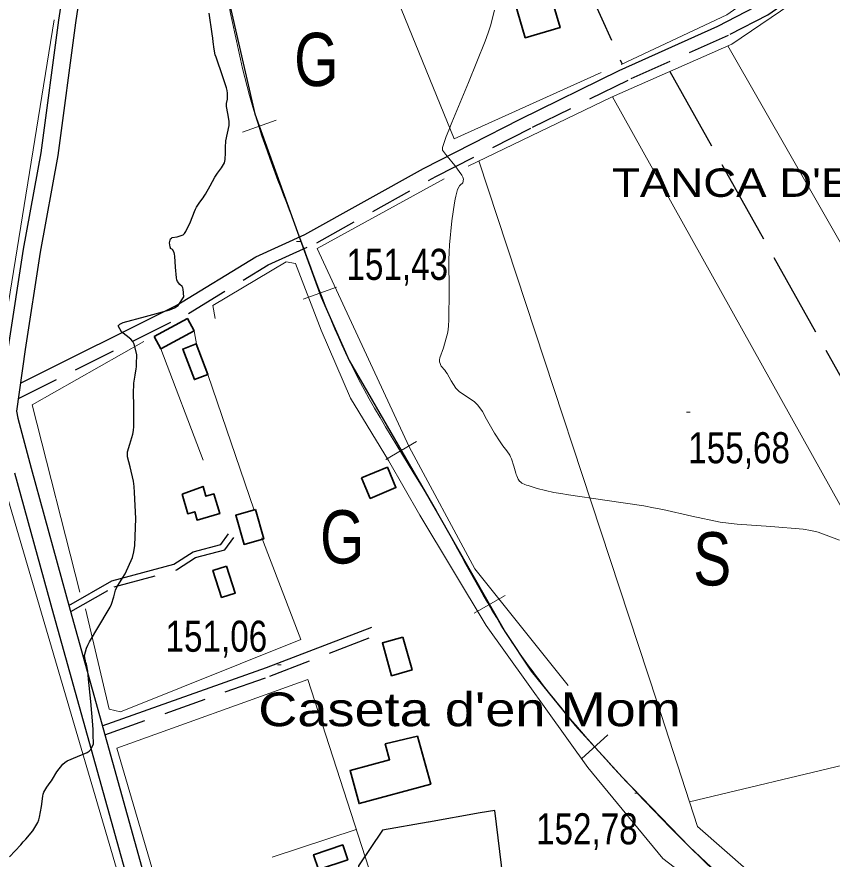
# Model space of a CAD drawing. Extents: x -807245 to 6129983, y -54972206 to 262146364.
# Drawn here: x 489087.2 to 489316.8, y 4382070.1 to 4382307.3 of the extents above; entities that cross this region are included whole.
import ezdxf
from ezdxf.enums import TextEntityAlignment as Align

# ---------------------------------------------------------------- set-up
doc = ezdxf.new("R2010")
doc.units = 0
doc.header["$LTSCALE"] = 4
doc.linetypes.add('LONG_DASHED', pattern=[7.5, 6, -1.5])
doc.linetypes.add('MEDIUM_DASHED', pattern=[4.5, 3, -1.5])
for name, color, linetype, lineweight in [('25', 7, 'LONG_DASHED', 25), ('27', 7, 'Continuous', 25), ('36', 7, 'Continuous', 25), ('38', 7, 'Continuous', 25), ('39', 7, 'Continuous', 13), ('47', 7, 'Continuous', 35), ('51', 7, 'Continuous', 13), ('7', 7, 'Continuous', 13), ('8', 7, 'Continuous', 25), ('9', 7, 'Continuous', 13)]:
    doc.layers.add(name, color=color, linetype=linetype, lineweight=lineweight)
doc.layers.add('31', color=7, linetype='Continuous')
doc.layers.add('5', color=7, linetype='Continuous')

msp = doc.modelspace()

# ---------------------------------------------------------------- linework, layer by layer
at = {"layer": '25'}
for points in [[(489168.58, 4382488.47), (489244.74, 4382322.63), (489257.64, 4382294.01)], [(489271.03, 4382291.96), (489360.67, 4382131.75), (489390.84, 4382082.83), (489403.32, 4382084.98), (489409.62, 4382085.53)], [(489237.15, 4382018.57), (489236.65, 4382020.96), (489234.84, 4382031.57), (489230.86, 4382042.28), (489226.41, 4382050.13), (489224.08, 4382060.73), (489224.23, 4382063.96), (489221.77, 4382083.78), (489217.59, 4382083.09), (489203.1, 4382080.52), (489202.95, 4382080.52), (489190.17, 4382078.29), (489183.34, 4382068.24), (489185.01, 4382057.02), (489191.66, 4382031), (489197.61, 4382022.73), (489196.92, 4382019.94), (489191.33, 4382015.01), (489174.9, 4382012.1), (489161.02, 4382005.12), (489155.08, 4382002.74), (489143.81, 4381998.77)]]:
    msp.add_lwpolyline(points, dxfattribs=at)
at = {"layer": '27'}
msp.add_spline([(491255.21, 4383970.03), (491244.34, 4383967.52), (491230.36, 4383957.66), (491230.81, 4383957.81), (491230.81, 4383957.81), (491220.15, 4383951.47), (491212.7, 4383943.01), (491205.06, 4383944.23), (491184.85, 4383957.71), (491152.82, 4383981.27), (491128.36, 4384004.58), (491128.29, 4384004.88), (491122.26, 4384021.39), (491095.75, 4384034.59), (491071.07, 4384059.32), (491064.71, 4384065.12)], degree=3, dxfattribs=at)
at = {"layer": '36'}
for points in [[(489077.26, 4382579.58), (489107.81, 4382506.6), (489121.68, 4382472.55), (489125.05, 4382466.03), (489123.49, 4382458.64), (489117.54, 4382425.29), (489109.13, 4382377.93), (489103.63, 4382337.83), (489098.85, 4382306.38), (489093.89, 4382269.07), (489088.94, 4382241.89), (489084.67, 4382214.35)], [(489108.41, 4382337.14), (489103.64, 4382305.7), (489098.67, 4382268.32), (489093.71, 4382241.09), (489089.45, 4382213.65), (489087.09, 4382196.26), (489087.39, 4382194.29), (489091.16, 4382180.17), (489102.15, 4382140.24), (489124.43, 4382060.27), (489131.12, 4382039.34), (489133.91, 4382029.11), (489136.02, 4382021.49), (489138.11, 4382014.49), (489143.72, 4381994.25), (489149.19, 4381977.02), (489163.16, 4381930.59), (489167.64, 4381912.18), (489169.68, 4381903.75), (489174.06, 4381887.79), (489180.31, 4381865.04), (489187.09, 4381842.68), (489195.69, 4381814.49)], [(489086.49, 4382178.91), (489097.49, 4382138.95), (489119.8, 4382058.89), (489126.48, 4382037.97), (489129.25, 4382027.83), (489131.37, 4382020.15), (489133.47, 4382013.15), (489139.09, 4381992.87), (489144.57, 4381975.59), (489158.49, 4381929.32), (489162.94, 4381911.04), (489165, 4381902.54), (489169.4, 4381886.51), (489175.67, 4381863.7), (489182.46, 4381841.27), (489190.64, 4381814.5)]]:
    msp.add_lwpolyline(points, dxfattribs=at)
at = {"layer": '38', "linetype": 'MEDIUM_DASHED'}
for points in [[(489087.58, 4382199.85), (489135.49, 4382223.82), (489157.97, 4382237.49), (489171.67, 4382243.71), (489205.12, 4382262.38), (489232.38, 4382276.24), (489260.17, 4382289.95), (489288.03, 4382302.42), (489298.63, 4382307.89), (489322.32, 4382324.43), (489353.36, 4382344.6), (489383.58, 4382364.21), (489405.61, 4382377.31), (489430.02, 4382388.68), (489458.01, 4382400.91), (489497.88, 4382418.16), (489523.2, 4382431.06), (489531.26, 4382436.02), (489537.97, 4382442.71), (489551.29, 4382462.89), (489558.74, 4382475.39), (489560.93, 4382480.17)], [(489102.32, 4382139.8), (489114.55, 4382146.79), (489132.12, 4382151.54), (489137.51, 4382155.03), (489145.68, 4382157.17), (489148.24, 4382160.65)], [(489111.92, 4382105.13), (489158.4, 4382121.62), (489188.03, 4382133.01)]]:
    msp.add_lwpolyline(points, dxfattribs=at)
at = {"layer": '38'}
for points in [[(489088.16, 4382204.17), (489131.98, 4382226.08), (489154.48, 4382239.77), (489168.21, 4382246), (489201.63, 4382264.65), (489228.92, 4382278.53), (489256.74, 4382292.26), (489284.59, 4382304.72), (489295.06, 4382310.12), (489318.69, 4382326.62), (489349.75, 4382346.8), (489380, 4382366.43), (489402.13, 4382379.59), (489426.62, 4382391), (489454.63, 4382403.24), (489460.15, 4382405.63)], [(489101.78, 4382141.56), (489113.86, 4382148.46), (489131.38, 4382153.2), (489136.78, 4382156.69), (489144.61, 4382158.74), (489146.79, 4382161.71)], [(489111.19, 4382107.61), (489157.5, 4382124.05), (489187.1, 4382135.42)]]:
    msp.add_lwpolyline(points, dxfattribs=at)
at = {"layer": '39'}
for p, q in [((489150.74, 4382274.85), (489160.14, 4382278.25)), ((489167.74, 4382227.83), (489177.14, 4382231.23)), ((489191.08, 4382182.7), (489199.73, 4382187.71)), ((489215.95, 4382139.36), (489224.63, 4382144.32)), ((489246.17, 4382098.32), (489253.54, 4382105.08))]:
    msp.add_line(p, q, dxfattribs=at)
at = {"layer": '39', "lineweight": 25}
msp.add_lwpolyline([(489144.72, 4382321.33), (489154.17, 4382280.07), (489166.23, 4382246.73), (489172.87, 4382228.35), (489180.75, 4382210.53), (489205.22, 4382168.24), (489224.8, 4382133.94), (489231.97, 4382122.99), (489244.36, 4382107.69), (489257.72, 4382093.12), (489276.58, 4382073.54), (489296.35, 4382054.96), (489327.82, 4382028.88), (489345.59, 4382015), (489364.04, 4382002), (489385.79, 4381989.49), (489408.28, 4381978.37), (489453.5, 4381958.06), (489487.73, 4381946.36), (489523.65, 4381936.12), (489543.6, 4381931.66), (489563.73, 4381928.23), (489620.66, 4381920.7)], dxfattribs=at)
at = {"layer": '39'}
msp.add_spline([(489117.55, 4382698.88), (489119.92, 4382672.68), (489122.01, 4382625.33), (489125.29, 4382585.13), (489126.65, 4382547.13), (489128.77, 4382508.18), (489130.39, 4382475.59), (489130.93, 4382447.55), (489133.21, 4382401.71), (489136.74, 4382363.61), (489144.72, 4382321.33), (489154.17, 4382280.07), (489166.23, 4382246.73), (489180.75, 4382210.53), (489205.22, 4382168.24), (489224.8, 4382133.94), (489257.72, 4382093.12), (489296.35, 4382054.96), (489327.82, 4382028.88), (489364.04, 4382002), (489408.28, 4381978.37), (489453.5, 4381958.06), (489487.73, 4381946.36), (489523.65, 4381936.12), (489563.73, 4381928.23), (489620.66, 4381920.7), (489680.32, 4381912.26), (489735.44, 4381905.59), (489799.91, 4381896.95), (489865.43, 4381887.81), (489926.74, 4381879.18), (489976.6, 4381873.08), (490039.39, 4381865.3), (490107.84, 4381856.38), (490175.25, 4381846.83), (490254.89, 4381836.5), (490348.33, 4381823.47), (490406.14, 4381813.57), (490409.06, 4381812.73)], degree=3, dxfattribs=at)
at = {"layer": '47'}
for points in [[(489227.52, 4382311.07), (489237.33, 4382313.92), (489240.12, 4382304.3), (489230.31, 4382301.45)], [(489125.85, 4382217.35), (489135.2, 4382222.36), (489137.07, 4382218.87), (489127.72, 4382213.86)], [(489137.67, 4382215.21), (489140.95, 4382206.6), (489137.14, 4382205.15), (489133.86, 4382213.76)], [(489184.25, 4382177.45), (489186.66, 4382171.7), (489193.91, 4382174.74), (489191.5, 4382180.49)], [(489133.72, 4382172.9), (489135.27, 4382167.38), (489137.24, 4382167.94), (489137.9, 4382165.6), (489144.27, 4382167.43), (489142.67, 4382172.96), (489140.42, 4382172.31), (489139.61, 4382175.07)], [(489154.37, 4382168.55), (489156.7, 4382160.31), (489151.13, 4382158.73), (489148.8, 4382166.97)], [(489146.24, 4382152.62), (489148.65, 4382145.04), (489144.79, 4382143.82), (489142.38, 4382151.4)], [(489195.88, 4382132.63), (489198.47, 4382123.38), (489192.67, 4382121.76), (489190.08, 4382131.01)], [(489200.01, 4382104.75), (489203.69, 4382091.18), (489183.54, 4382085.73), (489181.01, 4382095.05), (489192.13, 4382098.09), (489190.9, 4382102.56)], [(489172.11, 4382067.17), (489180.33, 4382069.93), (489178.94, 4382074.07), (489170.72, 4382071.31)]]:
    msp.add_lwpolyline(points, close=True, dxfattribs=at)
at = {"layer": '51'}
for p, q in [((489385.77, 4382049.89), (489254.86, 4382284.84)), ((489137.07, 4382218.87), (489137.87, 4382214.69)), ((489127.72, 4382213.86), (489139.59, 4382182.48)), ((489140.95, 4382206.6), (489153.95, 4382168.43)), ((489276.54, 4382086.23), (489355.1, 4382104.96)), ((489182.74, 4382078.4), (489159.06, 4382070.63))]:
    msp.add_line(p, q, dxfattribs=at)
for points in [[(489135.21, 4382457.32), (489210.35, 4382272.97), (489251.72, 4382291.65)], [(489257.37, 4382293.88), (489287.06, 4382307.95), (489308.19, 4382322.74), (489331.24, 4382338.4), (489358.34, 4382354.21), (489382.88, 4382370.8), (489400.25, 4382382.28), (489422.69, 4382392.07), (489442.08, 4382400.45), (489454.87, 4382405.6), (489456.51, 4382409.24), (489455.48, 4382411.92)], [(489214.27, 4382265.33), (489254.64, 4382284.74), (489288.52, 4382299.66), (489346.53, 4382339.11), (489369.81, 4382354.69)], [(489097.65, 4382306.5), (489080.2, 4382198.95), (488920.98, 4382110.04), (488849.95, 4382231.94)], [(489287.37, 4382299.16), (489484.32, 4381954.99), (489468.69, 4381959.59), (489464.17, 4381967.37)], [(489217.24, 4382266.76), (489267.45, 4382114.33), (489278.8, 4382079.25), (489336.68, 4382028.62), (489387.35, 4382050.58), (489418.8, 4381994.5), (489409.91, 4381986.13), (489409.83, 4381986.2)], [(489242.38, 4382119.03), (489216.16, 4382151.83), (489197.63, 4382186.22), (489171.73, 4382242.05), (489207.46, 4382261.76)], [(489142.99, 4382222.37), (489142.31, 4382226.03), (489163.04, 4382238.34), (489165.6, 4382237.87), (489172.84, 4382219.05), (489181.13, 4382199.96), (489191.79, 4382182.34), (489200.68, 4382167.01), (489219.28, 4382135.92), (489247.91, 4382095.9), (489269.09, 4382070.27), (489279.85, 4382062.03)], [(489104.85, 4382145.27), (489091.47, 4382198.07), (489122.96, 4382215.86)], [(489079.2, 4382189.93), (489144.68, 4381967.04), (489152.62, 4381940.14)], [(489106.53, 4382140.58), (489113.15, 4382112.37), (489116.39, 4382111.54), (489167.09, 4382131.93), (489156.19, 4382160.57)], [(489130.1, 4382057.4), (489127.67, 4382059.07), (489115.34, 4382101.32), (489169.07, 4382120.65), (489216.69, 4381973.42), (489152.19, 4381976.96), (489149.29, 4381979.22), (489129.52, 4382049.66), (489129.82, 4382053.41)]]:
    msp.add_lwpolyline(points, dxfattribs=at)
at = {"layer": '7'}
for p, q in [((489165.94, 4382244.11), (489166.94, 4382244.11)), ((489275.74, 4382195.97), (489276.74, 4382195.97)), ((489160.6, 4382124.82), (489161.6, 4382124.82)), ((489261.14, 4382088.63), (489262.14, 4382088.63))]:
    msp.add_line(p, q, dxfattribs=at)
at = {"layer": '8'}
for points in [[(489117.1, 4382221.29), (489123.35, 4382222.98), (489130.23, 4382224.84), (489131.54, 4382225.42), (489132.58, 4382226.03), (489134.22, 4382228.48), (489134, 4382230.62), (489133.89, 4382231.03), (489133.75, 4382231.37), (489133.05, 4382231.96), (489132.35, 4382232.76), (489132.21, 4382233.24), (489132.09, 4382233.83), (489131.86, 4382236.87), (489131.67, 4382239.9), (489131.58, 4382240.49), (489131.48, 4382240.97), (489130.97, 4382241.78), (489130.47, 4382242.12), (489130.38, 4382242.31), (489130.3, 4382242.54), (489130.15, 4382243.7), (489130.46, 4382244.81), (489130.67, 4382245.02), (489130.93, 4382245.18), (489132.32, 4382245.37), (489133.95, 4382245.95), (489134.36, 4382246.36), (489134.76, 4382246.88), (489136.08, 4382249.62), (489137.22, 4382252.56), (489137.51, 4382253.19), (489137.78, 4382253.75), (489138.69, 4382255.12), (489139.64, 4382256.36), (489139.95, 4382256.83), (489140.27, 4382257.36), (489141.58, 4382259.76), (489142.94, 4382262.22), (489143.29, 4382262.79), (489143.63, 4382263.32), (489144.77, 4382264.84), (489145.59, 4382266.23), (489145.73, 4382266.68), (489145.84, 4382267.15), (489145.92, 4382269.07), (489145.91, 4382271.19), (489145.97, 4382271.78), (489146.04, 4382272.38), (489146.52, 4382274.57), (489146.91, 4382276.77), (489146.94, 4382277.37), (489146.93, 4382277.98), (489146.58, 4382280.14), (489146.21, 4382282.07), (489146.18, 4382282.52), (489146.18, 4382282.94), (489146.46, 4382284.15), (489146.52, 4382285.84), (489146.39, 4382286.56), (489146.18, 4382287.39), (489144.9, 4382291.29), (489143.52, 4382295.16), (489143.25, 4382295.97), (489143.04, 4382296.67), (489142.68, 4382298.26), (489142.46, 4382300.33), (489142.32, 4382301.33), (489142.16, 4382302.52), (489141.29, 4382308.38)], [(489085.09, 4382070.77), (489088.24, 4382074.11), (489088.98, 4382074.93), (489089.67, 4382075.7), (489091.68, 4382078.09), (489093.06, 4382080.41), (489093.34, 4382081.13), (489093.58, 4382081.89), (489094.09, 4382084.94), (489094.46, 4382087.78), (489094.61, 4382088.4), (489094.78, 4382088.96), (489095.58, 4382090.39), (489096.58, 4382091.65), (489096.89, 4382092.1), (489097.2, 4382092.59), (489098.42, 4382094.72), (489100.1, 4382096.84), (489100.7, 4382097.33), (489101.37, 4382097.78), (489104.27, 4382099.01), (489106.96, 4382100.12), (489107.49, 4382100.48), (489107.92, 4382100.86), (489108.7, 4382102.43), (489108.69, 4382105.32), (489108.63, 4382106.54), (489108.54, 4382107.93), (489108, 4382114.46), (489107.37, 4382120.76), (489107.23, 4382122.01), (489107.1, 4382123.05), (489106.76, 4382125), (489106.52, 4382125.7), (489106.47, 4382125.96), (489106.41, 4382126.23), (489106.24, 4382127.42), (489106.76, 4382129.51), (489107.14, 4382130.35), (489107.63, 4382131.31), (489110.26, 4382135.7), (489112.91, 4382140.09), (489113.41, 4382141.05), (489113.82, 4382141.89), (489114.44, 4382144), (489114.92, 4382145.82), (489115.23, 4382146.48), (489115.62, 4382147.21), (489117.67, 4382150.45), (489119.69, 4382155.07), (489120.06, 4382156.69), (489120.35, 4382158.44), (489120.7, 4382165.99), (489120.33, 4382173.4), (489120.17, 4382175.07), (489119.97, 4382176.57), (489119.04, 4382180.62), (489118.36, 4382183.4), (489118.32, 4382184.11), (489118.35, 4382184.78), (489119, 4382186.98), (489119.83, 4382189.76), (489119.97, 4382190.8), (489120.07, 4382191.95), (489120.12, 4382197.1), (489120.05, 4382202.12), (489120.07, 4382203.2), (489120.12, 4382204.14), (489120.43, 4382206.42), (489120.78, 4382208.17), (489120.84, 4382208.77), (489120.88, 4382209.43), (489120.91, 4382212.26), (489120.21, 4382215.17), (489119.79, 4382215.87), (489119.28, 4382216.54), (489116.61, 4382218.58), (489115.64, 4382220.33), (489116.19, 4382220.81), (489117.1, 4382221.29)]]:
    msp.add_lwpolyline(points, dxfattribs=at)
at = {"layer": '9'}
for points in [[(489209.69, 4382277.62), (489214.34, 4382288.88), (489218.99, 4382300.45), (489219.87, 4382302.83), (489220.58, 4382304.85), (489221.68, 4382309.19)], [(489318.84, 4382159.93), (489312.78, 4382162.22), (489310.76, 4382162.68), (489308.59, 4382163.06), (489299.52, 4382163.82), (489289.99, 4382164.42), (489287.54, 4382164.71), (489285.17, 4382165.04), (489277.28, 4382166.68), (489269.03, 4382168.57), (489266.43, 4382169.07), (489263.7, 4382169.56), (489252.7, 4382171.23), (489242.54, 4382172.7), (489240.34, 4382173.06), (489238.41, 4382173.4), (489233.65, 4382174.48), (489231.14, 4382175.29), (489230.63, 4382175.47), (489230.21, 4382175.63), (489229.32, 4382176.03), (489228.95, 4382176.35), (489228.84, 4382176.47), (489228.74, 4382176.59), (489228.34, 4382177.11), (489227.91, 4382178.03), (489227.77, 4382178.4), (489227.63, 4382178.83), (489227.08, 4382180.81), (489226.41, 4382182.89), (489226.21, 4382183.38), (489225.99, 4382183.83), (489225.11, 4382185.14), (489224.02, 4382186.54), (489223.66, 4382187.05), (489223.28, 4382187.61), (489221.71, 4382190.05), (489220.14, 4382192.67), (489219.75, 4382193.34), (489219.39, 4382193.99), (489218.25, 4382196.14), (489216.99, 4382197.98), (489216.54, 4382198.44), (489216.06, 4382198.88), (489213.95, 4382200.27), (489211.8, 4382201.73), (489211.3, 4382202.21), (489210.82, 4382202.72), (489209.43, 4382204.86), (489208.3, 4382206.91), (489208, 4382207.37), (489207.7, 4382207.78), (489206.67, 4382208.91), (489206.16, 4382210.21), (489206.2, 4382210.73), (489206.31, 4382211.34), (489207.34, 4382214.12), (489208.51, 4382218.57), (489208.71, 4382220.23), (489208.85, 4382222.06), (489208.9, 4382230.21), (489208.83, 4382238.91), (489208.89, 4382241.09), (489208.98, 4382243.17), (489209.62, 4382249.88), (489210.39, 4382254.92), (489210.57, 4382255.96), (489210.74, 4382256.84), (489211.22, 4382258.74), (489211.69, 4382259.56), (489211.85, 4382259.76), (489212.03, 4382259.96), (489212.79, 4382260.57), (489212.95, 4382261.65), (489212.75, 4382262.14), (489212.45, 4382262.71), (489210.46, 4382265.46), (489208.3, 4382268.13), (489207.89, 4382268.65), (489207.56, 4382269.07), (489207.04, 4382269.8), (489207.04, 4382269.98), (489207.04, 4382270.06), (489207.03, 4382270.15), (489207, 4382270.54), (489208.09, 4382273.64), (489208.8, 4382275.43), (489209.69, 4382277.62)]]:
    msp.add_lwpolyline(points, dxfattribs=at)

# ---------------------------------------------------------------- texts
at = {"layer": '31', "width": 0.8}
for s, p in [('G', (489171.49, 4382287.84)), ('G', (489178.79, 4382153.36)), ('S', (489282.97, 4382147.18))]:
    msp.add_text(s, height=15, dxfattribs=at).set_placement(p, align=Align.CENTER)
at = {"layer": '5', "width": 1.2}
for s, height, p in [("TANCA D'EN TOMEU MEMES", 8, (489254.77, 4382256.63)), ("Caseta d'en Mom", 9.5, (489155.14, 4382107.53))]:
    msp.add_text(s, height=height, dxfattribs=at).set_placement(p)
at = {"layer": '7', "width": 0.8}
for s, p in [('151,43', (489179.96, 4382233.25)), ('155,68', (489276.24, 4382181.6)), ('151,06', (489129.03, 4382128.5)), ('152,78', (489233.36, 4382074.26))]:
    msp.add_text(s, height=8.75, dxfattribs=at).set_placement(p)

doc.saveas('drawing.dxf')
